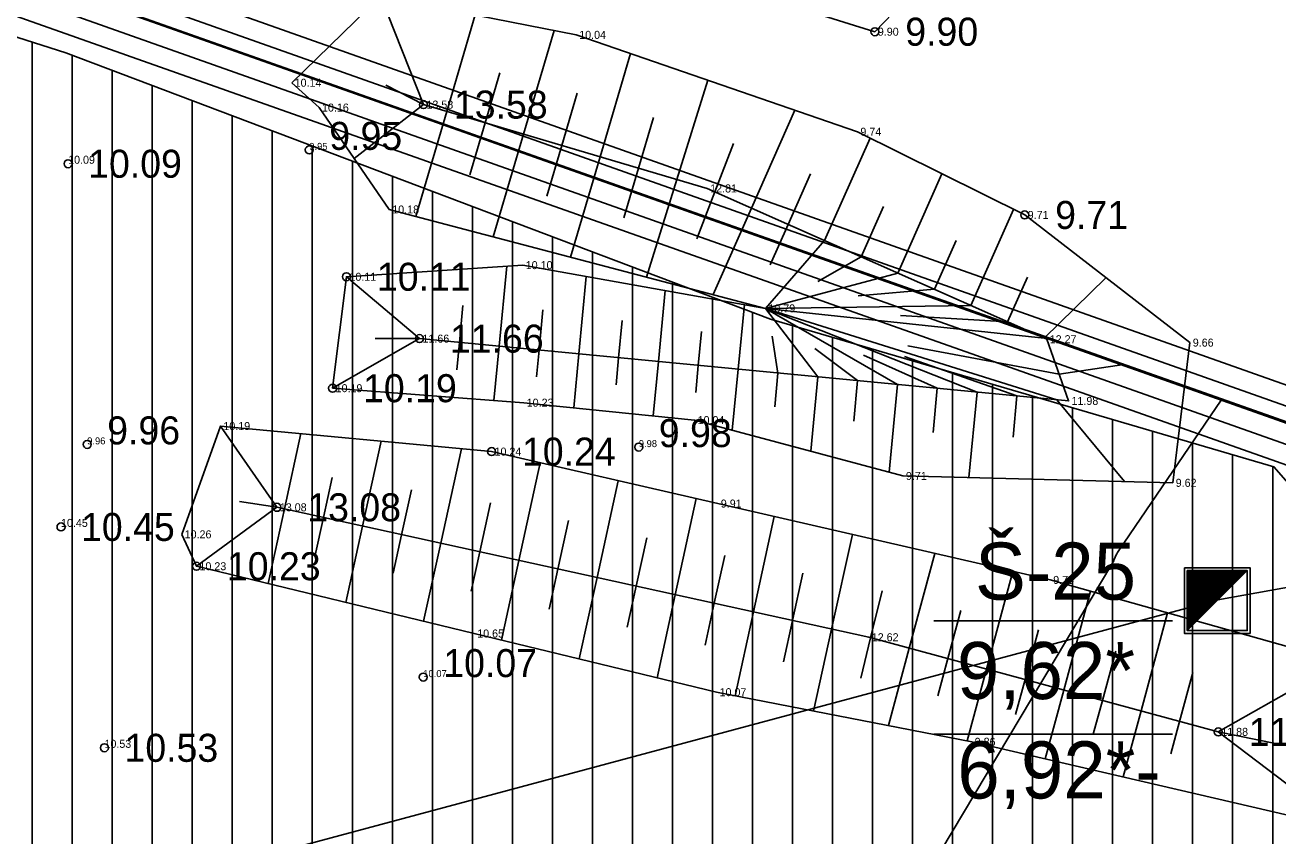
# Model space of a CAD drawing. Extents: x 433497 to 434382, y 6534486 to 6534993.
# Drawn here: x 434060.9 to 434123.5, y 6534836.3 to 6534876.8 of the extents above; entities that cross this region are included whole.
import ezdxf

# ---------------------------------------------------------------- set-up
doc = ezdxf.new("R2010")
doc.units = 0
for name, color, linetype in [('Default', 7, 'Continuous'), ('GEOLPUNKT', 7, 'Continuous'), ('kataster', 7, 'Continuous'), ('KORGUS', 7, 'Continuous'), ('KORGUS-EH2000', 7, 'Continuous'), ('l__x00e4__bil__x00f5__iked', 7, 'Continuous'), ('Lamami horisontaal', 7, 'Continuous'), ('MAAMUDEL-EH2000', 7, 'Continuous'), ('MOOTKORG-EH2000', 7, 'Continuous'), ('PIIR', 7, 'Continuous'), ('RELJEEF', 7, 'Continuous'), ('Täide', 7, 'Continuous')]:
    doc.layers.add(name, color=color, linetype=linetype)

msp = doc.modelspace()

# ---------------------------------------------------------------- linework, layer by layer
at = {"layer": 'Default'}
msp.add_lwpolyline([(433617.12, 6534791.025), (433632.75, 6534606.045), (434137.38, 6534796.515), (434127.69, 6534855.6), (433968.21, 6534911.925), (433942.38, 6534904.035), (433920.99, 6534907.275)], close=True, dxfattribs=at)
msp.add_lwpolyline([(433617.12, 6534791.025), (433632.75, 6534606.045), (434137.38, 6534796.515), (434127.69, 6534855.6), (433968.21, 6534911.925), (433942.38, 6534904.035), (433920.99, 6534907.275)], close=True, dxfattribs=at)
msp.add_lwpolyline([(433617.12, 6534791.025), (433632.75, 6534606.045), (434137.38, 6534796.515), (434127.69, 6534855.6), (433968.21, 6534911.925), (433942.38, 6534904.035), (433920.99, 6534907.275)], close=True, dxfattribs=at)
at = {"layer": 'GEOLPUNKT'}
for p, q in [((434118.939, 6534846.545), (434121.939, 6534849.545)), ((434118.939, 6534846.576), (434121.909, 6534849.545)), ((434118.939, 6534846.646), (434121.838, 6534849.545)), ((434118.939, 6534846.717), (434121.767, 6534849.545)), ((434118.939, 6534846.788), (434121.697, 6534849.545)), ((434118.939, 6534846.858), (434121.626, 6534849.545)), ((434118.939, 6534846.929), (434121.555, 6534849.545)), ((434118.939, 6534847), (434121.485, 6534849.545)), ((434118.939, 6534847.071), (434121.414, 6534849.545)), ((434118.939, 6534847.141), (434121.343, 6534849.545)), ((434118.939, 6534847.212), (434121.272, 6534849.545)), ((434118.939, 6534847.283), (434121.202, 6534849.545)), ((434118.939, 6534847.353), (434121.131, 6534849.545)), ((434118.939, 6534847.424), (434121.06, 6534849.545)), ((434118.939, 6534847.495), (434120.99, 6534849.545)), ((434118.939, 6534847.566), (434120.919, 6534849.545)), ((434118.939, 6534847.636), (434120.848, 6534849.545)), ((434118.939, 6534847.707), (434120.777, 6534849.545)), ((434118.939, 6534847.778), (434120.707, 6534849.545)), ((434118.939, 6534847.848), (434120.636, 6534849.545)), ((434118.939, 6534847.919), (434120.565, 6534849.545)), ((434118.939, 6534847.99), (434120.495, 6534849.545)), ((434118.939, 6534848.061), (434120.424, 6534849.545)), ((434118.939, 6534848.131), (434120.353, 6534849.545)), ((434118.939, 6534848.202), (434120.282, 6534849.545)), ((434118.939, 6534848.273), (434120.212, 6534849.545)), ((434118.939, 6534848.343), (434120.141, 6534849.545)), ((434118.939, 6534848.414), (434120.07, 6534849.545)), ((434118.939, 6534848.485), (434120, 6534849.545)), ((434118.939, 6534848.556), (434119.929, 6534849.545)), ((434118.939, 6534848.626), (434119.858, 6534849.545)), ((434118.939, 6534848.697), (434119.787, 6534849.545)), ((434118.939, 6534848.768), (434119.717, 6534849.545)), ((434118.939, 6534848.838), (434119.646, 6534849.545)), ((434118.939, 6534848.909), (434119.575, 6534849.545)), ((434118.939, 6534848.98), (434119.505, 6534849.545)), ((434118.939, 6534849.05), (434119.434, 6534849.545)), ((434118.939, 6534849.121), (434119.363, 6534849.545)), ((434118.939, 6534849.192), (434119.292, 6534849.545)), ((434118.939, 6534849.263), (434119.222, 6534849.545)), ((434118.939, 6534849.333), (434119.151, 6534849.545)), ((434118.939, 6534849.404), (434119.08, 6534849.545)), ((434118.939, 6534849.475), (434119.01, 6534849.545)), ((434120.439, 6534848.045), (434120.439, 6534848.045))]:
    msp.add_line(p, q, dxfattribs=at)
for points in [[(434118.798, 6534849.686), (434122.08, 6534849.686), (434122.08, 6534846.404), (434118.798, 6534846.404)], [(434118.939, 6534849.545), (434121.939, 6534849.545), (434121.939, 6534846.545), (434118.939, 6534846.545)]]:
    msp.add_lwpolyline(points, close=True, dxfattribs=at)
for points in [[(434106.283, 6534847.029), (434118.199, 6534847.029)], [(434106.283, 6534841.375), (434118.199, 6534841.375)]]:
    msp.add_lwpolyline(points, dxfattribs=at)
at = {"layer": 'kataster'}
msp.add_lwpolyline([(433617.102, 6534791.002), (433632.769, 6534606.029), (434137.446, 6534796.469), (434127.827, 6534855.589), (433950.026, 6534918.39)], close=True, dxfattribs=at)
at = {"layer": 'KORGUS'}
for centre in [(434103.33, 6534876.46), (434080.77, 6534872.82), (434063.009, 6534869.865), (434110.821, 6534867.307), (434076.92, 6534864.22), (434080.57, 6534861.13), (434076.229, 6534858.654), (434084.172, 6534855.488), (434073.441, 6534852.704), (434062.652, 6534851.725), (434069.424, 6534849.76), (434120.494, 6534841.488), (434064.825, 6534840.691)]:
    msp.add_circle(centre, 0.2, dxfattribs=at)
at = {"layer": 'KORGUS-EH2000'}
for centre in [(434075.061, 6534870.557), (434063.961, 6534855.846), (434091.531, 6534855.711), (434080.759, 6534844.222)]:
    msp.add_circle(centre, 0.2, dxfattribs=at)
at = {"layer": 'l__x00e4__bil__x00f5__iked'}
msp.add_lwpolyline([(433620.07, 6534691.039), (433627.105, 6534692.187), (433736.834, 6534712.709), (433742.792, 6534710.723), (433822.234, 6534766.498), (433986.579, 6534812.177), (434120.472, 6534848.091), (434132.163, 6534850.175)], dxfattribs=at)
at = {"layer": 'Lamami horisontaal'}
msp.add_lwpolyline([(433993.085, 6534819.831), (434065.946, 6534798.347), (434073.345, 6534797.199), (434079.829, 6534798.389), (434085.398, 6534801.916), (434090.054, 6534807.779), (434115.176, 6534849.864), (434115.208, 6534849.92), (434115.238, 6534849.976), (434115.267, 6534850.033), (434115.294, 6534850.091), (434115.398, 6534850.325), (434115.425, 6534850.383), (434115.455, 6534850.439), (434115.487, 6534850.494), (434115.522, 6534850.548), (434120.641, 6534858.055)], dxfattribs=at)
at = {"layer": 'PIIR'}
for points in [[(434138.342, 6534801.592), (434129.36, 6534856.88), (433968.248, 6534913.871)], [(433632.021, 6534604.835), (434138.248, 6534795.936), (434128.468, 6534856.135), (433968.226, 6534912.818), (433942.33, 6534904.85), (433920.952, 6534908.165), (433616.327, 6534791.524), (433632.021, 6534604.835)], [(433632.732, 6534605.959), (434137.353, 6534796.454), (434127.754, 6534855.539), (433968.208, 6534911.976), (433942.39, 6534904.031), (433921.04, 6534907.341), (433617.174, 6534790.992), (433632.732, 6534605.959)]]:
    msp.add_lwpolyline(points, dxfattribs=at)
for points in [[(433618.234, 6534790.327), (433921.149, 6534906.313), (433942.464, 6534903.008), (433968.187, 6534910.923), (434126.862, 6534854.794), (434136.235, 6534797.101), (433633.617, 6534607.362)], [(433619.24, 6534789.695), (433634.52, 6534608.851), (434135.141, 6534797.808), (434125.908, 6534854.108), (433968.165, 6534909.82), (433942.53, 6534901.99), (433921.212, 6534905.219)], [(433619.24, 6534789.695), (433634.52, 6534608.851), (434135.141, 6534797.808), (434125.908, 6534854.108), (433968.165, 6534909.82), (433942.53, 6534901.99), (433921.212, 6534905.219)]]:
    msp.add_lwpolyline(points, close=True, dxfattribs=at)
at = {"layer": 'RELJEEF'}
for p, q in [((434080.77, 6534872.82), (434078.619, 6534878.238)), ((434081.928, 6534872.478), (434083.354, 6534877.302)), ((434085.764, 6534871.344), (434087.294, 6534876.522)), ((434089.6, 6534870.211), (434091.124, 6534875.366)), ((434084.585, 6534874.412), (434083.846, 6534871.911)), ((434080.77, 6534872.82), (434078.893, 6534873.797)), ((434093.436, 6534869.077), (434094.977, 6534874.04)), ((434088.456, 6534873.398), (434087.682, 6534870.778)), ((434080.77, 6534872.82), (434077.299, 6534870.133)), ((434081.928, 6534872.478), (434080.379, 6534867.234)), ((434097.163, 6534867.648), (434099.334, 6534872.539)), ((434083.08, 6534869.318), (434083.846, 6534871.911)), ((434092.267, 6534872.179), (434091.518, 6534869.644)), ((434085.764, 6534871.344), (434084.249, 6534866.217)), ((434100.82, 6534866.026), (434103.093, 6534871.148)), ((434086.933, 6534868.243), (434087.682, 6534870.778)), ((434096.26, 6534870.869), (434095.335, 6534868.459)), ((434089.6, 6534870.211), (434088.119, 6534865.199)), ((434090.786, 6534867.168), (434091.518, 6534869.644)), ((434100.112, 6534869.361), (434098.992, 6534866.837)), ((434104.476, 6534864.403), (434106.678, 6534869.366)), ((434093.436, 6534869.077), (434091.922, 6534864.2)), ((434094.437, 6534866.117), (434095.335, 6534868.459)), ((434097.163, 6534867.648), (434095.246, 6534863.327)), ((434103.767, 6534867.736), (434102.648, 6534865.214)), ((434108.132, 6534862.781), (434110.264, 6534867.585)), ((434098.099, 6534864.824), (434098.992, 6534866.837)), ((434100.82, 6534866.026), (434097.86, 6534862.64)), ((434107.387, 6534866.034), (434106.304, 6534863.592)), ((434102.648, 6534865.214), (434100.477, 6534863.98)), ((434080.57, 6534861.13), (434076.92, 6534864.22)), ((434084.552, 6534860.748), (434084.935, 6534864.75)), ((434088.533, 6534860.367), (434088.904, 6534864.237)), ((434104.476, 6534864.403), (434097.86, 6534862.64)), ((434110.952, 6534864.205), (434109.96, 6534861.97)), ((434111.788, 6534861.158), (434114.876, 6534864.173)), ((434092.515, 6534859.985), (434092.855, 6534863.532)), ((434106.304, 6534863.592), (434102.489, 6534863.259)), ((434082.737, 6534862.778), (434082.561, 6534860.939)), ((434086.736, 6534862.573), (434086.543, 6534860.557)), ((434096.497, 6534859.603), (434096.806, 6534862.828)), ((434108.132, 6534862.781), (434097.86, 6534862.64)), ((434112.424, 6534858.076), (434097.86, 6534862.64)), ((434100.479, 6534859.221), (434097.86, 6534862.64)), ((434104.46, 6534858.84), (434097.86, 6534862.64)), ((434108.442, 6534858.458), (434097.86, 6534862.64)), ((434111.788, 6534861.158), (434097.86, 6534862.64)), ((434109.96, 6534861.97), (434104.607, 6534862.284)), ((434090.702, 6534862.03), (434090.524, 6534860.176)), ((434080.57, 6534861.13), (434076.229, 6534858.654)), ((434080.57, 6534861.13), (434078.348, 6534861.13)), ((434094.668, 6534861.487), (434094.506, 6534859.794)), ((434098.488, 6534859.412), (434098.205, 6534861.253)), ((434082.429, 6534859.566), (434082.561, 6534860.939)), ((434084.552, 6534860.748), (434084.292, 6534858.043)), ((434086.414, 6534859.218), (434086.543, 6534860.557)), ((434102.47, 6534859.031), (434100.323, 6534860.638)), ((434112.539, 6534859.35), (434104.978, 6534860.774)), ((434088.533, 6534860.367), (434088.276, 6534857.676)), ((434090.395, 6534858.824), (434090.524, 6534860.176)), ((434092.515, 6534859.985), (434092.255, 6534857.27)), ((434094.375, 6534858.431), (434094.506, 6534859.794)), ((434106.451, 6534858.649), (434102.758, 6534860.299)), ((434110.433, 6534858.267), (434104.81, 6534860.242)), ((434115.769, 6534859.844), (434112.539, 6534859.35)), ((434096.497, 6534859.603), (434096.205, 6534856.555)), ((434098.326, 6534857.721), (434098.488, 6534859.412)), ((434100.479, 6534859.221), (434100.122, 6534855.505)), ((434102.275, 6534857.005), (434102.47, 6534859.031)), ((434104.46, 6534858.84), (434104.04, 6534854.456)), ((434106.24, 6534856.443), (434106.451, 6534858.649)), ((434108.442, 6534858.458), (434108.033, 6534854.186)), ((434110.235, 6534856.201), (434110.433, 6534858.267)), ((434112.424, 6534858.076), (434115.815, 6534853.989)), ((434073.441, 6534852.704), (434070.619, 6534856.763)), ((434073.816, 6534852.622), (434074.641, 6534856.384)), ((434077.723, 6534851.765), (434078.654, 6534856.007)), ((434081.63, 6534850.908), (434082.666, 6534855.63)), ((434085.537, 6534850.051), (434086.607, 6534854.929)), ((434076.209, 6534854.195), (434075.77, 6534852.193)), ((434080.168, 6534853.577), (434079.677, 6534851.336)), ((434089.444, 6534849.193), (434090.506, 6534854.034)), ((434073.441, 6534852.704), (434071.575, 6534852.993)), ((434084.121, 6534852.928), (434083.584, 6534850.479)), ((434093.352, 6534848.336), (434094.405, 6534853.139)), ((434073.441, 6534852.704), (434069.424, 6534849.76)), ((434073.816, 6534852.622), (434072.998, 6534848.895)), ((434075.356, 6534850.309), (434075.77, 6534852.193)), ((434077.723, 6534851.765), (434076.887, 6534847.954)), ((434088.024, 6534852.052), (434087.491, 6534849.622)), ((434097.259, 6534847.479), (434098.304, 6534852.243)), ((434079.254, 6534849.41), (434079.677, 6534851.336)), ((434091.927, 6534851.176), (434091.398, 6534848.765)), ((434101.166, 6534846.622), (434102.208, 6534851.347)), ((434081.63, 6534850.908), (434080.776, 6534847.013)), ((434083.152, 6534848.511), (434083.584, 6534850.479)), ((434105.049, 6534845.667), (434106.329, 6534850.401)), ((434085.537, 6534850.051), (434084.665, 6534846.072)), ((434095.83, 6534850.299), (434095.305, 6534847.908)), ((434087.05, 6534847.612), (434087.491, 6534849.622)), ((434089.444, 6534849.193), (434088.553, 6534845.131)), ((434099.733, 6534849.423), (434099.212, 6534847.051)), ((434108.91, 6534844.622), (434110.231, 6534849.505)), ((434090.948, 6534846.713), (434091.398, 6534848.765)), ((434103.694, 6534848.531), (434103.118, 6534846.189)), ((434112.771, 6534843.578), (434114.106, 6534848.511)), ((434093.352, 6534848.336), (434092.442, 6534844.19)), ((434094.846, 6534845.814), (434095.305, 6534847.908)), ((434097.259, 6534847.479), (434096.34, 6534843.291)), ((434107.63, 6534847.549), (434106.979, 6534845.145)), ((434116.632, 6534842.533), (434117.956, 6534847.427)), ((434098.758, 6534844.98), (434099.212, 6534847.051)), ((434101.166, 6534846.622), (434100.263, 6534842.529)), ((434102.623, 6534844.178), (434103.118, 6534846.189)), ((434111.511, 6534846.576), (434110.841, 6534844.1)), ((434105.049, 6534845.667), (434104.003, 6534841.802)), ((434115.366, 6534845.512), (434114.702, 6534843.055)), ((434106.475, 6534843.282), (434106.979, 6534845.145)), ((434120.494, 6534841.488), (434126.661, 6534844.978)), ((434108.91, 6534844.622), (434107.94, 6534841.037)), ((434119.222, 6534844.448), (434118.563, 6534842.011)), ((434110.366, 6534842.347), (434110.841, 6534844.1)), ((434112.771, 6534843.578), (434111.841, 6534840.141)), ((434114.246, 6534841.372), (434114.702, 6534843.055)), ((434116.632, 6534842.533), (434115.741, 6534839.237)), ((434118.127, 6534840.398), (434118.563, 6534842.011)), ((434120.494, 6534841.488), (434126.831, 6534836.665)), ((434120.494, 6534841.488), (434123.361, 6534840.904))]:
    msp.add_line(p, q, dxfattribs=at)
for points in [[(434079.87, 6534888.68), (434077.61, 6534885.94), (434082.14, 6534882.09), (434091.47, 6534880.17), (434103.33, 6534876.46), (434107.924, 6534881.239)], [(434074.181, 6534873.912), (434078.619, 6534878.238), (434088.405, 6534876.303), (434102.458, 6534871.463), (434110.821, 6534867.307), (434119.071, 6534860.931), (434118.218, 6534853.928), (434104.734, 6534854.27), (434094.322, 6534857.06), (434085.78, 6534857.93), (434076.229, 6534858.654)], [(434075.55, 6534872.67), (434074.181, 6534873.912)], [(434076.229, 6534858.654), (434076.92, 6534864.22), (434085.731, 6534864.802), (434097.86, 6534862.64), (434079.06, 6534867.58), (434075.55, 6534872.67)], [(434080.57, 6534861.13), (434113.01, 6534858.02), (434111.92, 6534861.1), (434094.95, 6534868.63), (434080.77, 6534872.82)], [(434126.831, 6534836.665), (434126.661, 6534844.978), (434112.095, 6534849.077), (434095.482, 6534852.891), (434084.172, 6534855.488), (434070.619, 6534856.763), (434068.684, 6534851.354)], [(434120.494, 6534841.488), (434103.027, 6534846.214), (434073.441, 6534852.704)], [(434068.684, 6534851.354), (434069.424, 6534849.76), (434083.306, 6534846.401), (434095.42, 6534843.47), (434108.17, 6534840.992), (434126.831, 6534836.665)]]:
    msp.add_lwpolyline(points, dxfattribs=at)
at = {"layer": 'Täide'}
for p, q in [((434061.213, 6534770.471), (434061.213, 6534875.946)), ((434063.213, 6534771.29), (434063.213, 6534875.289)), ((434065.213, 6534771.962), (434065.213, 6534874.534)), ((434067.213, 6534772.635), (434067.213, 6534873.778)), ((434069.213, 6534773.307), (434069.213, 6534873.023)), ((434071.213, 6534773.979), (434071.213, 6534872.268)), ((434073.213, 6534774.651), (434073.213, 6534871.512)), ((434075.213, 6534775.323), (434075.213, 6534870.757)), ((434077.213, 6534776.152), (434077.213, 6534870.002)), ((434079.213, 6534777.334), (434079.213, 6534869.246)), ((434081.213, 6534778.516), (434081.213, 6534868.491)), ((434083.213, 6534779.673), (434083.213, 6534867.736)), ((434085.213, 6534780.367), (434085.213, 6534866.98)), ((434087.213, 6534781.061), (434087.213, 6534866.225)), ((434089.213, 6534781.755), (434089.213, 6534865.469)), ((434091.213, 6534782.449), (434091.213, 6534864.714)), ((434093.213, 6534783.144), (434093.213, 6534863.959)), ((434095.213, 6534783.838), (434095.213, 6534863.203)), ((434097.213, 6534784.532), (434097.213, 6534862.448)), ((434099.213, 6534785.226), (434099.213, 6534861.785)), ((434101.213, 6534785.934), (434101.213, 6534861.198)), ((434103.213, 6534786.679), (434103.213, 6534860.611)), ((434105.213, 6534787.424), (434105.213, 6534860.024)), ((434107.213, 6534788.169), (434107.213, 6534859.437)), ((434109.213, 6534788.914), (434109.213, 6534858.85)), ((434111.213, 6534789.649), (434111.213, 6534858.263)), ((434113.213, 6534790.344), (434113.213, 6534857.676)), ((434115.213, 6534791.039), (434115.213, 6534857.089)), ((434117.213, 6534791.735), (434117.213, 6534856.502)), ((434119.213, 6534792.43), (434119.213, 6534855.915)), ((434121.213, 6534793.125), (434121.213, 6534855.328)), ((434123.213, 6534793.82), (434123.213, 6534854.741))]:
    msp.add_line(p, q, dxfattribs=at)
msp.add_lwpolyline([(434053.953, 6534766.741), (434062.043, 6534770.897), (434076.601, 6534775.79), (434083.107, 6534779.636), (434100.67, 6534785.732), (434110.817, 6534789.511), (434130.115, 6534796.22), (434132.899, 6534799.258), (434133.017, 6534809.88), (434125.182, 6534852.548), (434123.278, 6534854.722), (434098.113, 6534862.108), (434062.901, 6534875.407), (434022.093, 6534888.443), (434021.059, 6534887.256), (434037.893, 6534864.165), (434021.392, 6534791.18), (434023.3, 6534781.148), (434025.663, 6534773.898), (434039.607, 6534770.357), (434045.083, 6534767.989), (434045.714, 6534765.502), (434044.882, 6534761.539)], dxfattribs=at)

# ---------------------------------------------------------------- texts
at = {"layer": 'GEOLPUNKT'}
for s, p in [('Š-25', (434108.334, 6534848.091)), ('9,62*', (434107.432, 6534843.126)), ('6,92*-', (434107.45, 6534838.161))]:
    msp.add_text(s, height=2.85, dxfattribs=at).set_placement(p)
at = {"layer": 'KORGUS-EH2000'}
for s, p in [(' 9.90', (434104.33, 6534875.76)), (' 13.58', (434081.77, 6534872.12)), ('9.95', (434076.061, 6534870.557)), ('10.09', (434064.009, 6534869.165)), (' 9.71', (434111.821, 6534866.607)), (' 10.11', (434077.92, 6534863.52)), (' 11.66', (434081.57, 6534860.43)), (' 10.19', (434077.229, 6534857.954)), ('9.96', (434064.961, 6534855.846)), ('9.98', (434092.531, 6534855.711)), (' 10.24', (434085.172, 6534854.788)), (' 13.08', (434074.441, 6534852.004)), ('10.45', (434063.652, 6534851.025)), (' 10.23', (434070.424, 6534849.06)), ('10.07', (434081.759, 6534844.222)), (' 11.88', (434121.494, 6534840.788)), ('10.53', (434065.825, 6534839.991))]:
    msp.add_text(s, height=1.4, dxfattribs=at).set_placement(p)
at = {"layer": 'MAAMUDEL-EH2000'}
for s, p in [(' 10.04', (434088.405, 6534876.103)), (' 9.90', (434103.33, 6534876.26)), (' 10.14', (434074.181, 6534873.712)), (' 13.58', (434080.77, 6534872.62)), (' 10.16', (434075.55, 6534872.47)), (' 10.16', (434075.55, 6534872.47)), (' 9.74', (434102.458, 6534871.263)), ('10.09', (434063.009, 6534869.865)), (' 12.81', (434094.95, 6534868.43)), (' 10.18', (434079.06, 6534867.38)), (' 9.71', (434110.821, 6534867.107)), (' 10.10', (434085.731, 6534864.602)), (' 10.11', (434076.92, 6534864.02)), (' 10.79', (434097.86, 6534862.44)), (' 11.66', (434080.57, 6534860.93)), (' 12.27', (434111.92, 6534860.9)), (' 9.66', (434119.071, 6534860.731)), (' 10.19', (434076.229, 6534858.454)), (' 10.23', (434085.78, 6534857.73)), (' 11.98', (434113.01, 6534857.82)), (' 10.04', (434094.322, 6534856.86)), (' 10.19', (434070.619, 6534856.563)), (' 10.24', (434084.172, 6534855.288)), (' 9.71', (434104.734, 6534854.07)), (' 9.62', (434118.218, 6534853.728)), (' 13.08', (434073.441, 6534852.504)), (' 9.91', (434095.482, 6534852.691)), ('10.45', (434062.652, 6534851.725)), (' 10.26', (434068.684, 6534851.154)), (' 10.23', (434069.424, 6534849.56)), (' 9.73', (434112.095, 6534848.877)), (' 10.65', (434083.306, 6534846.201)), (' 12.62', (434103.027, 6534846.014)), (' 10.07', (434095.42, 6534843.27)), (' 11.88', (434120.494, 6534841.288)), ('10.53', (434064.825, 6534840.691)), (' 9.86', (434108.17, 6534840.792))]:
    msp.add_text(s, height=0.4, dxfattribs=at).set_placement(p)
at = {"layer": 'MOOTKORG-EH2000'}
for s, p in [('9.95', (434075.061, 6534870.557)), ('9.96', (434063.961, 6534855.846)), ('9.98', (434091.531, 6534855.711)), ('10.07', (434080.759, 6534844.222))]:
    msp.add_text(s, height=0.35, dxfattribs=at).set_placement(p)

doc.saveas('drawing.dxf')
